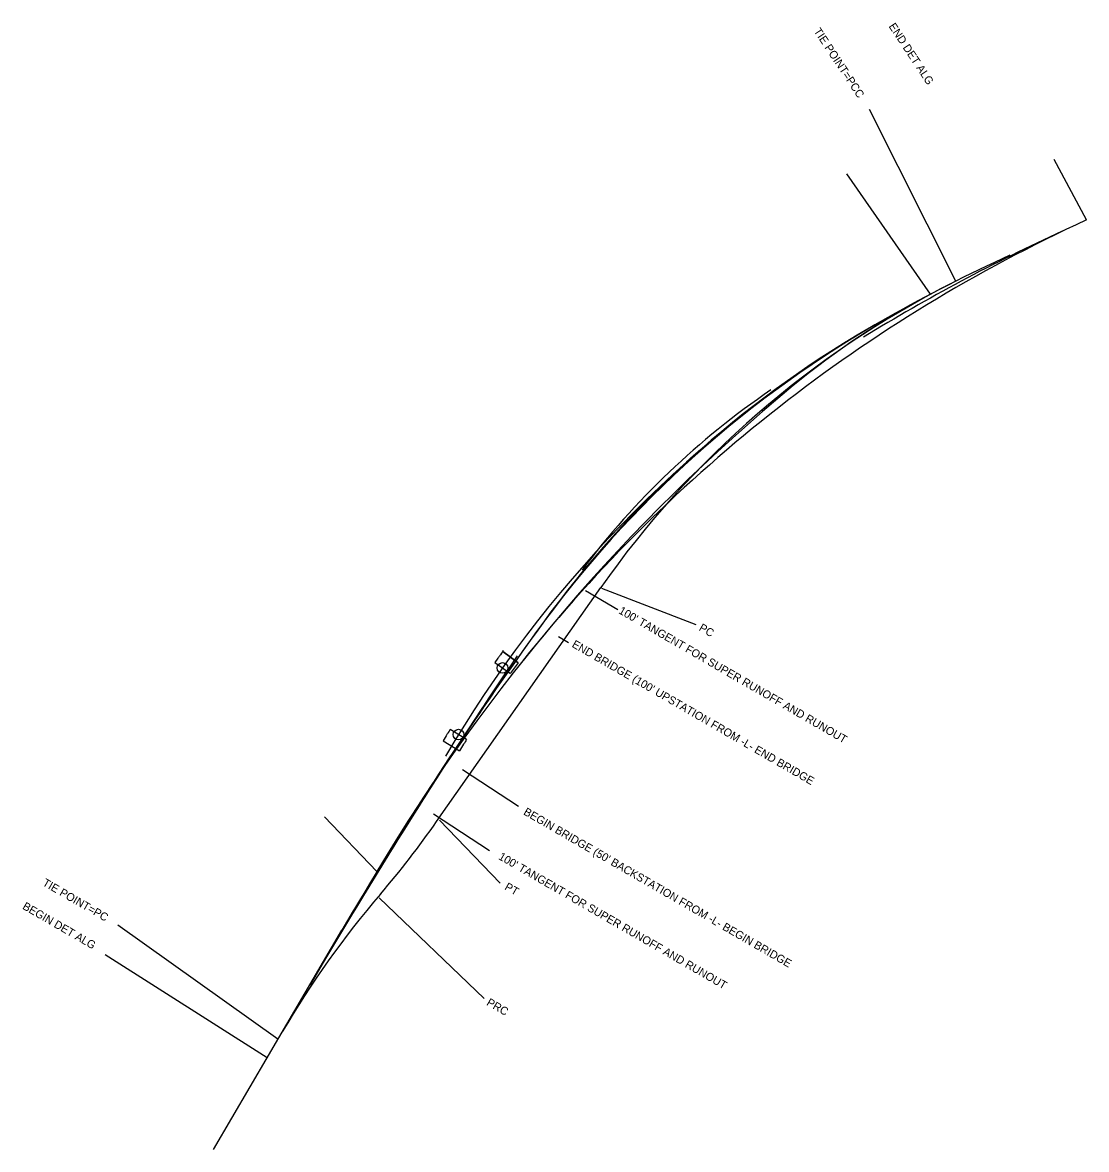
# Model space of a CAD drawing. Extents: x 2379484 to 2381484, y 331424 to 333541.
import ezdxf

# ---------------------------------------------------------------- set-up
doc = ezdxf.new("R2010")
doc.units = 0
for name, color, linetype in [('_P_RDY_Guardrail_Anchor_Unit_Cell', 7, 'Continuous'), ('Draft_Plan_Labels', 7, 'Continuous'), ('P_NCDOT_Roadway_Bridge', 7, 'Continuous'), ('P_RDY_Bridge_Approach_Slab', 7, 'Continuous'), ('P_RDY_DSN_Text', 7, 'Continuous'), ('P_RDY_Equation_Symbol', 7, 'Continuous'), ('P_RDY_Horizontal_Alignment_Station_Label', 7, 'Continuous'), ('P_RDY_Lane_Arrow_Cell', 7, 'Continuous'), ('P_RDY_Paved_Shoulder', 7, 'Continuous'), ('P_RDY_Structure_Anchor_Unit_Cell', 7, 'Continuous'), ('Prop Horizontal Alignment Station Label', 7, 'Continuous')]:
    doc.layers.add(name, color=color, linetype=linetype)

msp = doc.modelspace()

# ---------------------------------------------------------------- linework, layer by layer
at = {"layer": '_P_RDY_Guardrail_Anchor_Unit_Cell'}
msp.add_arc((2390650.2, 325452.9), 12344.3, 146.18352, 149.20485, dxfattribs=at)
at = {"layer": 'Draft_Plan_Labels'}
for centre in [(2380386, 332328.6), (2380303.2, 332203.4)]:
    msp.add_circle(centre, 10, dxfattribs=at)
at = {"layer": 'P_NCDOT_Roadway_Bridge'}
for centre, radius, start, end in [((2382697.9, 330525.1), 2910.7, 114.6596, 141.3841), ((2382910.8, 329941.4), 3530, 114.6596, 121.535), ((2382080.2, 331238), 2000, 120.1715, 144.0254), ((2381733.7, 331610.3), 1500, 124.2013, 143.0215), ((2386191.3, 328253.9), 7080, 144.0254, 149.60684)]:
    msp.add_arc(centre, radius, start, end, dxfattribs=at)
at = {"layer": 'P_RDY_Bridge_Approach_Slab'}
msp.add_line((2380386.4, 332359.3), (2380415.3, 332338), dxfattribs=at)
msp.add_arc((2390018.2, 325870.8), 11586.6, 145.99128, 149.60684, dxfattribs=at)
at = {"layer": 'P_RDY_DSN_Text'}
for p, q in [((2380415.3, 332338), (2380386.4, 332359.3)), ((2380371.5, 332339), (2380400.7, 332317.9)), ((2380282.4, 332204.5), (2380282.4, 332204.5)), ((2380318.2, 332194), (2380287.7, 332213.1)), ((2380274.5, 332191.7), (2380305.2, 332172.9))]:
    msp.add_line(p, q, dxfattribs=at)
for points in [[(2380387.5, 332361.1), (2380385.7, 332358.6), (2380383.8, 332356.1), (2380382, 332353.5), (2380381.1, 332352.3), (2380380.2, 332351), (2380379.2, 332349.7), (2380378.3, 332348.5), (2380377.4, 332347.2), (2380371.5, 332339)], [(2380287.7, 332213.1), (2380287.3, 332212.5), (2380285.6, 332209.8), (2380284, 332207.2), (2380282.4, 332204.5)]]:
    msp.add_lwpolyline(points, dxfattribs=at)
for centre, radius, start, end in [((2379733.6, 332776), 774.4, 327.4521, 327.61), ((2382266.8, 330970.2), 2301.9, 143.5442, 144.1617), ((2384928.2, 329333.2), 5461.6, 148.2827, 148.4406), ((2385054.9, 329254.9), 5574.5, 148.2839, 148.4346), ((2381372.7, 331532), 1245, 147.8781, 148.3447)]:
    msp.add_arc(centre, radius, start, end, dxfattribs=at)
at = {"layer": 'P_RDY_Equation_Symbol'}
for p, q in [((2380262.2, 332039.8), (2380570.8, 332479.8)), ((2379842.6, 331423.8), (2380084.3, 331835.9)), ((2379842.6, 331423.8), (2380084.3, 331835.9))]:
    msp.add_line(p, q, dxfattribs=at)
for centre, radius, start, end in [((2382633, 330287), 3100, 114.6596, 119.4199), ((2382633, 330287), 3100, 114.6596, 119.4199), ((2382044.4, 331446.1), 1800, 116.92, 144.9522), ((2382044.4, 331446.1), 1800, 116.92, 144.9522), ((2382124.6, 331188.5), 2065, 119.4199, 144.1843), ((2382124.6, 331188.5), 2065, 119.4199, 144.1843), ((2386191.3, 328253.9), 7080, 144.18428, 149.60684), ((2386191.3, 328253.9), 7080, 144.18428, 149.60684), ((2386191.3, 328253.9), 7080, 144.18428, 149.60684), ((2378788.6, 333073.5), 1800, 319.4679, 324.9522), ((2378788.6, 333073.5), 1800, 319.4679, 324.9522), ((2381524.7, 330733.9), 1800, 139.4672, 149.6068), ((2381524.7, 330733.9), 1800, 139.4672, 149.6068)]:
    msp.add_arc(centre, radius, start, end, dxfattribs=at)
at = {"layer": 'P_RDY_Horizontal_Alignment_Station_Label'}
for p, q in [((2381483.5, 333170.4), (2381422.8, 333283.8)), ((2381190.2, 333030.8), (2381033.4, 333256.9)), ((2380149.5, 331945.9), (2380051.7, 332048.7))]:
    msp.add_line(p, q, dxfattribs=at)
for centre, radius, start, end in [((2381888.3, 331703.1), 1500, 117.7379, 129.5824), ((2383181.8, 330138.6), 3530, 129.5824, 149.2049), ((2390018.2, 325870.8), 11586.6, 146.16079, 149.60684)]:
    msp.add_arc(centre, radius, start, end, dxfattribs=at)
at = {"layer": 'P_RDY_Lane_Arrow_Cell'}
for p, q in [((2381238.1, 333055.5), (2381075.8, 333377.7)), ((2380602.8, 332437.5), (2380542.2, 332473.2)), ((2380572.3, 332478.6), (2380749.1, 332410.3)), ((2380510.2, 332376), (2380491.4, 332387.1)), ((2380311.1, 332137.9), (2380416.3, 332069)), ((2380256.3, 332054.3), (2380361.5, 331985.3)), ((2380267.6, 332042.3), (2380381.5, 331924.3)), ((2380154.3, 331896.5), (2380351.7, 331707.7)), ((2379964, 331630.8), (2379662.9, 331845.2)), ((2379943.8, 331596.3), (2379639.3, 331789.6))]:
    msp.add_line(p, q, dxfattribs=at)
at = {"layer": 'P_RDY_Paved_Shoulder'}
msp.add_arc((2382262.2, 330998.3), 2300, 122.3416, 149.5863, dxfattribs=at)
at = {"layer": 'P_RDY_Structure_Anchor_Unit_Cell'}
msp.add_line((2379943.8, 331596.3), (2379964, 331630.8), dxfattribs=at)
at = {"layer": 'Prop Horizontal Alignment Station Label'}
msp.add_line((2379842.6, 331423.8), (2380084.3, 331835.9), dxfattribs=at)
for centre, radius, start, end in [((2382633, 330287), 3100, 114.6596, 119.4199), ((2382124.6, 331188.5), 2065, 119.4199, 144.1843), ((2386191.3, 328253.9), 7080, 144.18428, 149.60684)]:
    msp.add_arc(centre, radius, start, end, dxfattribs=at)

# ---------------------------------------------------------------- texts
at = {"layer": 'P_RDY_Lane_Arrow_Cell'}
for s, height, rotation, p in [('TIE POINT=PCC', 15.038, 303.4476, (2380970.3, 333525.2)), ('END DET ALG', 15.038, 303.4476, (2381111.1, 333534.4)), ("100' TANGENT FOR SUPER RUNOFF AND RUNOUT", 15.038, 329.9589, (2380602.9, 332432.1)), ('PC', 15.04, 329.9589, (2380753.9, 332400)), ("END BRIDGE (100' UPSTATION FROM -L- END BRIDGE", 15.038, 329.9589, (2380515.1, 332368.9)), ("BEGIN BRIDGE (50' BACKSTATION FROM -L- BEGIN BRIDGE", 15.038, 329.9589, (2380424.1, 332054)), ("100' TANGENT FOR SUPER RUNOFF AND RUNOUT", 15.038, 329.9589, (2380377.1, 331970)), ('TIE POINT=PC', 15.038, 329.9589, (2379520.1, 331920.8)), ('PT', 15.04, 329.9589, (2380388.7, 331913.2)), ('BEGIN DET ALG', 15.038, 329.9589, (2379482.5, 331876.6)), ('PRC', 15.04, 329.9589, (2380354.7, 331695.9))]:
    msp.add_text(s, height=height, rotation=rotation, dxfattribs=at).set_placement(p)

doc.saveas('drawing.dxf')
